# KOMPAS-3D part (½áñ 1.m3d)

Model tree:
1. Эскиз:1
2. Операция выдавливания:1
     Расстояние 1 = 20
3. Эскиз:2
4. Операция выдавливания:2
     Расстояние 1 = 400
5. Эскиз:3
6. Вырезать элемент выдавливания:1
     Расстояние 1 = 70
7. Эскиз:4
8. Вырезать элемент выдавливания:2
     Расстояние 1 = 2
9. Эскиз:5
10. Эскиз:11
11. Вырезать элемент выдавливания:7
     Расстояние 1 = 30
12. Операция выдавливания:3
     Расстояние 1 = 16.96
13. Эскиз:13
14. Вырезать элемент выдавливания:9
     Расстояние 1 = 70
15. Эскиз:14
16. Вырезать элемент выдавливания:10
     Расстояние 1 = 80
